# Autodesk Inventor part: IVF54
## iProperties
Created: 2009-10
Part Number: IVF54
Material: Sondermaterial siehe Beschreibung
Document SubType Name: Blech
Designer: Gawin
Surface Area: 570.329 cm^2
Volume: 40.5539 cm^3
Sheet Metal Rule: R2,5
Author: Gawin
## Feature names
1. Spiegeln1 [Mirror]
2. Spiegeln2 [Mirror]
3. Grobblech2
4. Ausklinkung1
